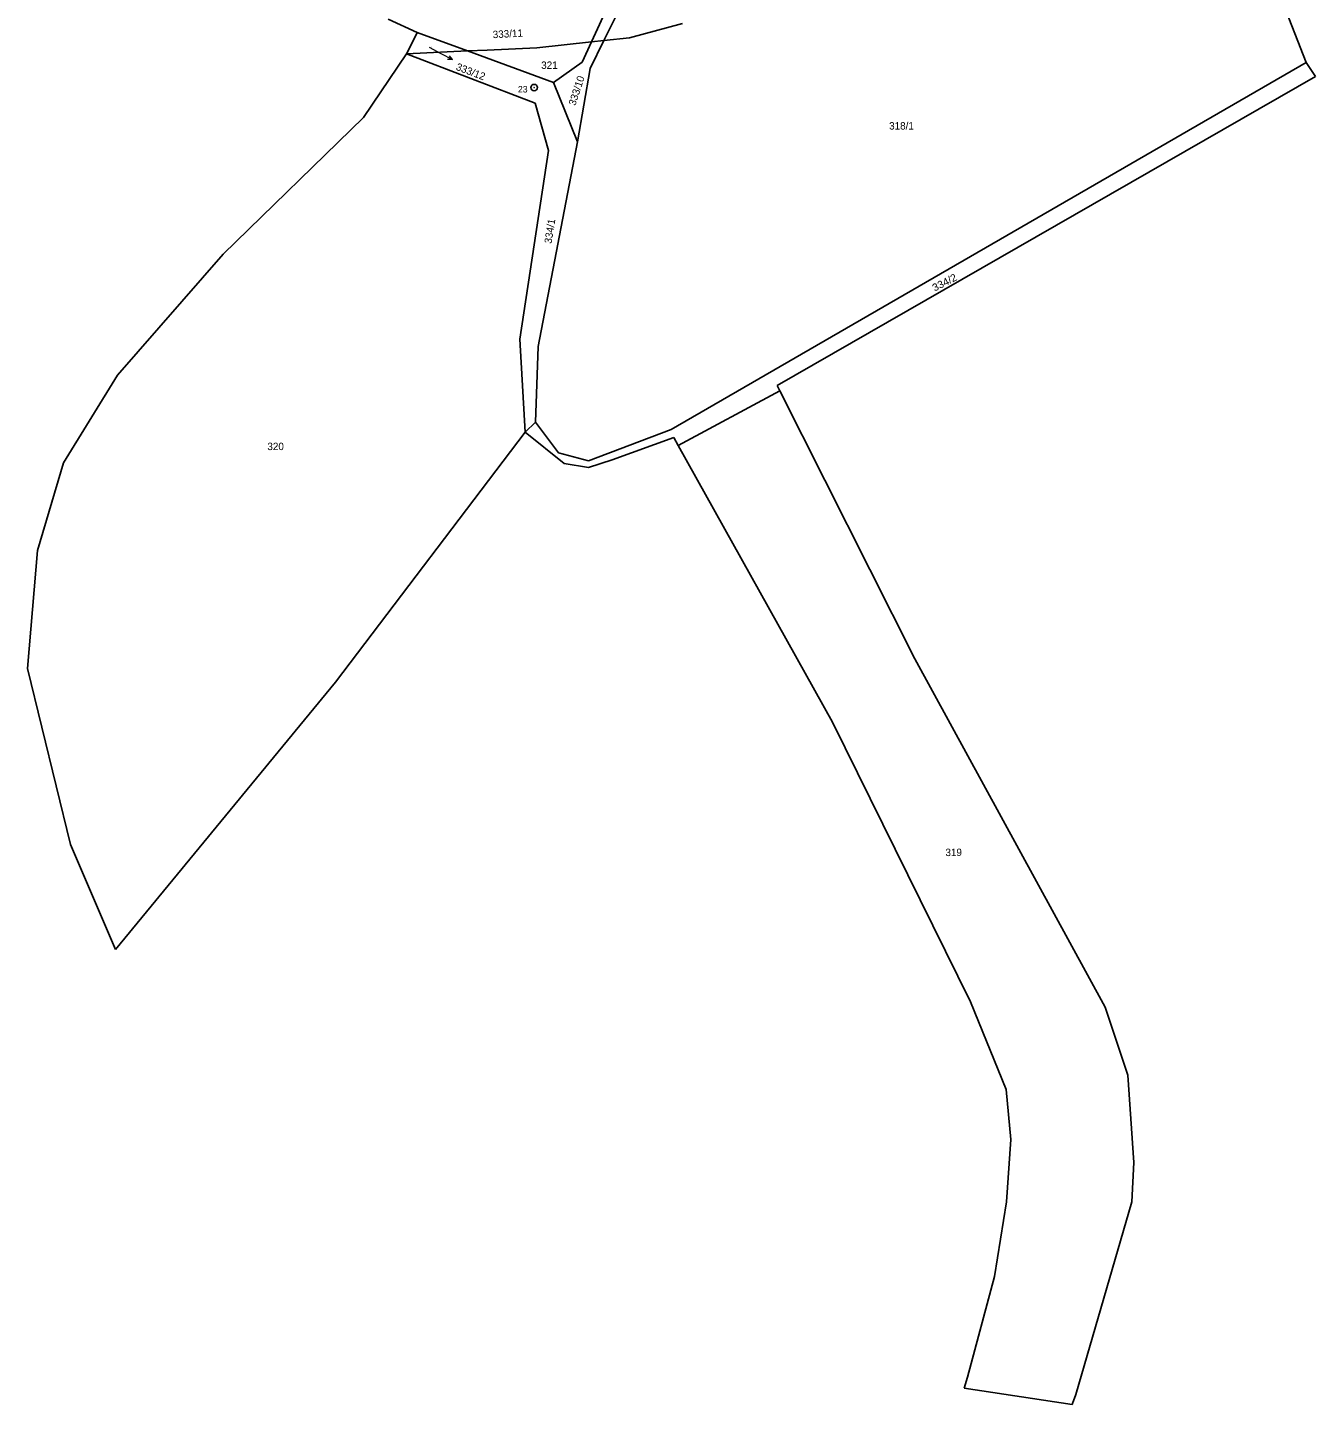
# Model space of a CAD drawing. Extents: x -645290 to -643454, y -1064771 to -1062356.
# Drawn here: x -644994.2 to -644698, y -1064771.3 to -1064454.7 of the extents above; entities that cross this region are included whole.
import ezdxf
from ezdxf.enums import TextEntityAlignment as Align

# ---------------------------------------------------------------- set-up
doc = ezdxf.new("R2010")
doc.units = 0
doc.header["$LTSCALE"] = 0.68
for name, color, linetype, lineweight in [('1', 7, 'Continuous', 25), ('7', 7, 'Continuous', 13), ('8', 7, 'Continuous', 25)]:
    doc.layers.add(name, color=color, linetype=linetype, lineweight=lineweight)
doc.layers.add('2', color=7, linetype='Continuous')

msp = doc.modelspace()

# ---------------------------------------------------------------- linework, layer by layer
at = {"layer": '1'}
for p, q in [((-644700.13, -1064462.71), (-644713.81, -1064427.79)), ((-644860.43, -1064449.12), (-644864.48, -1064457.95)), ((-644861.67, -1064457.65), (-644858.45, -1064451.16)), ((-644911.29, -1064452.76), (-644904.59, -1064455.83)), ((-644843.56, -1064453.69), (-644855.74, -1064457.02)), ((-644904.91, -1064456.46), (-644907.02, -1064460.68)), ((-644904.59, -1064455.83), (-644904.91, -1064456.46)), ((-644904.59, -1064455.83), (-644893.04, -1064460.05)), ((-644864.84, -1064464.06), (-644861.67, -1064457.65)), ((-644861.67, -1064457.65), (-644864.48, -1064457.95)), ((-644855.74, -1064457.02), (-644861.67, -1064457.65)), ((-644907.02, -1064460.68), (-644916.91, -1064475.32)), ((-644893.04, -1064460.05), (-644907.02, -1064460.68)), ((-644877.43, -1064472.08), (-644907.02, -1064460.68)), ((-644888.46, -1064459.85), (-644893.04, -1064460.05)), ((-644873.23, -1064467.3), (-644893.04, -1064460.05)), ((-644877.06, -1064459.29), (-644888.46, -1064459.85)), ((-644864.48, -1064457.95), (-644877.06, -1064459.29)), ((-644864.48, -1064457.95), (-644866.64, -1064462.65)), ((-644866.64, -1064462.65), (-644873.23, -1064467.3)), ((-644867.74, -1064480.96), (-644864.84, -1064464.06)), ((-644700.13, -1064462.71), (-644846.2, -1064547.13)), ((-644700.13, -1064462.71), (-644698.02, -1064465.9)), ((-644867.74, -1064480.96), (-644873.23, -1064467.3)), ((-644821.82, -1064536.99), (-644698.02, -1064465.9)), ((-644877.43, -1064472.08), (-644874.35, -1064482.93)), ((-644916.91, -1064475.32), (-644949.18, -1064506.77)), ((-644880.96, -1064526.29), (-644874.35, -1064482.93)), ((-644876.76, -1064527.98), (-644867.74, -1064480.96)), ((-644949.18, -1064506.77), (-644973.5, -1064534.6)), ((-644879.77, -1064547.74), (-644880.96, -1064526.29)), ((-644877.36, -1064545.44), (-644876.76, -1064527.98)), ((-644821.82, -1064536.99), (-644821.2, -1064538.23)), ((-644844.57, -1064550.8), (-644821.2, -1064538.23)), ((-644821.2, -1064538.23), (-644790.11, -1064599.86)), ((-644877.36, -1064545.44), (-644879.77, -1064547.74)), ((-644872.1, -1064552.48), (-644877.36, -1064545.44)), ((-644923.4, -1064605.24), (-644879.77, -1064547.74)), ((-644879.77, -1064547.74), (-644870.79, -1064554.93)), ((-644846.2, -1064547.13), (-644865.19, -1064554.31)), ((-644859.76, -1064554.09), (-644845.59, -1064548.97)), ((-644845.59, -1064548.97), (-644844.57, -1064550.8)), ((-644865.19, -1064554.31), (-644872.1, -1064552.48)), ((-644809.1, -1064614.4), (-644844.57, -1064550.8)), ((-644870.79, -1064554.93), (-644865.19, -1064555.85)), ((-644865.19, -1064555.85), (-644859.76, -1064554.09)), ((-644991.88, -1064574.91), (-644994.18, -1064602.03)), ((-644746.34, -1064679.91), (-644790.11, -1064599.86)), ((-644994.18, -1064602.03), (-644984.28, -1064642.53)), ((-644973.92, -1064666.7), (-644923.4, -1064605.24)), ((-644809.1, -1064614.4), (-644777.34, -1064678.75)), ((-644984.28, -1064642.53), (-644973.92, -1064666.7)), ((-644777.34, -1064678.75), (-644769.16, -1064698.84)), ((-644741.17, -1064695.6), (-644746.34, -1064679.91)), ((-644739.81, -1064715.67), (-644741.17, -1064695.6)), ((-644769.16, -1064698.84), (-644768.09, -1064710.37)), ((-644768.09, -1064710.37), (-644769.05, -1064724.68)), ((-644740.22, -1064724.72), (-644739.81, -1064715.67)), ((-644769.05, -1064724.68), (-644771.85, -1064741.88)), ((-644753.16, -1064769.01), (-644740.22, -1064724.72)), ((-644778.79, -1064767.54), (-644753.97, -1064771.31)), ((-644753.97, -1064771.31), (-644753.89, -1064771.09)), ((-644753.16, -1064769.01), (-644753.89, -1064771.09))]:
    msp.add_line(p, q, dxfattribs=at)
for points in [[(-644973.5, -1064534.6), (-644985.92, -1064554.77), (-644991.88, -1064574.91)], [(-644771.85, -1064741.88), (-644778, -1064765), (-644778.79, -1064767.54)]]:
    msp.add_lwpolyline(points, dxfattribs=at)
at = {"layer": '7'}
msp.add_line((-644896.47, -1064462.039), (-644897.119, -1064461.127), dxfattribs=at)
msp.add_lwpolyline([(-644901.83, -1064459.18), (-644899.12, -1064460.63), (-644896.47, -1064462.039), (-644897.59, -1064462.011)], dxfattribs=at)
at = {"layer": '8'}
for radius in [0.75, 0.03]:
    msp.add_circle((-644877.69, -1064468.4698), radius, dxfattribs=at)

# ---------------------------------------------------------------- texts
at = {"layer": '2'}
for s, rotation, p in [('333/11', 3, (-644887.167, -1064457.114)), ('333/12', 339, (-644895.819, -1064464.335)), ('333/10', 72, (-644868.205, -1064472.721)), ('334/1', 81, (-644873.69, -1064504.426))]:
    msp.add_text(s, height=1.7, rotation=rotation, dxfattribs=at).set_placement(p)
for s, height, p in [('333/12', 0.2, (-644901.83, -1064459.229)), ('321', 1.7, (-644876.07, -1064464.165)), ('318/1', 1.7, (-644796.06, -1064478.115)), ('320', 1.7, (-644939.03, -1064551.834)), ('319', 1.7, (-644783.11, -1064645.195))]:
    msp.add_text(s, height=height, dxfattribs=at).set_placement(p)
at = {"layer": '2', "width": 1.05}
msp.add_text('334/2', height=1.7, rotation=27, dxfattribs=at).set_placement((-644785.597, -1064515.388))
at = {"layer": '8'}
msp.add_text('23', height=1.5, dxfattribs=at).set_placement((-644879.189, -1064469.587), align=Align.RIGHT)

doc.saveas('drawing.dxf')
